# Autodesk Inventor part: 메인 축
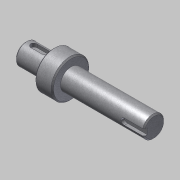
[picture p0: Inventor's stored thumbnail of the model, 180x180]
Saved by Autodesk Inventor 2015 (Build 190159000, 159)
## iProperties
Created: 2016-04
Part Number: 메인 축
Document SubType Name: Modeling
Designer: mdu
Density: 7.86 g/cm^3
Mass: 230.24 g
Surface Area: 74.3518 cm^2
Volume: 29.2926 cm^3
Material: 강철, 연강
Appearance: 금속-강(스테인리스, 브러시됨)
Author: mdu
Revision Number: 1
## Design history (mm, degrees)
sketch "스케치1"
  geometry: L1 (10.497, -57.5)-(112.497, -57.5); L2 (10.497, -66)-(32.497, -66); L3 (32.497, -72.5)-(46.5, -72.5); L4 (46.5, -66)-(112.497, -66); L5 (112.497, -66)-(112.497, -57.5); L6 (10.497, -66)-(10.497, -57.5); L7 (46.5, -69.749)-(46.5, -45.251) reference; L8 (46.5, -72.5)-(46.5, -66); L9 (32.497, -72.5)-(32.497, -66); L10 (32.497, -35)-(32.497, -80) reference; 3 further points
  constraints: 16 end point, 3 point on line, 2 parallel, 2 perpendicular, 1 collinear, 1 horizontal, 1 midpoint
  dimensions: "d0" = 17 diameter of L4 L1; "d1" = 30 diameter of L3 L1; "d2" = 22 distance of L2.start L2.end; "d3" = 65.99692 distance of L4.start L4.end (derived); "d5" = 17 diameter of L2 L1; "d19" = 80 distance between parallel lines of L5 L9
revolve "회전1" sketch "스케치1" stored, may be unused: angle "d4" = 90 deg
chamfer "모따기1" distance "d6" = 1; stored, may be unused: second distance "d7" = 2, angle "d8" = 45 deg
node "작업 평면1"
sketch "스케치2"
  geometry: L1 (-11, -7.5)-(-11, 7.5) reference; L2 (-4.5, 2.5)-(4.5, 2.5); L3 (4.5, -2.5)-(-4.5, -2.5); A1 r 2.5 centre (4.5, 0) between (4.5, -2.5) and (4.5, 2.5); A2 r 2.5 centre (-4.5, 0) between (-4.5, 2.5) and (-4.5, -2.5); 2 further points
  constraints: 4 end point, 4 point on circle, 4 tangent, 2 centre point, 1 horizontal alignment, 1 midpoint, 1 parallel, 1 perpendicular
  dimensions: "d9" = 5 distance between parallel lines of L3 L2; "d10" = 14 dimension on A1 A2; "d11" = 4 distance edge to line of A2 L1
extrude "돌출1" cut sketch "스케치2" distance "d12" = 3; taper "d13" = 0 deg
node "작업 평면2"
sketch "스케치3"
  geometry: L1 (32.998, 7.5)-(32.998, -7.5) reference; L2 (32.998, 2.5)-(17.498, 2.5); L3 (17.498, -2.5)-(32.998, -2.5); A1 r 2.5 centre (17.498, 0) between (17.498, 2.5) and (17.498, -2.5); 2 further points
  constraints: 4 end point, 2 perpendicular, 2 point on circle, 2 point on line, 2 tangent, 1 centre point, 1 horizontal alignment, 1 midpoint
  dimensions: "d14" = 5 distance between parallel lines of L3 L2; "d15" = 18 dimension on A1 L1
extrude "돌출2" cut sketch "스케치3" distance "d16" = 3; taper "d17" = 0 deg
node "솔리드1"
node "참조4"
node "참조5"
